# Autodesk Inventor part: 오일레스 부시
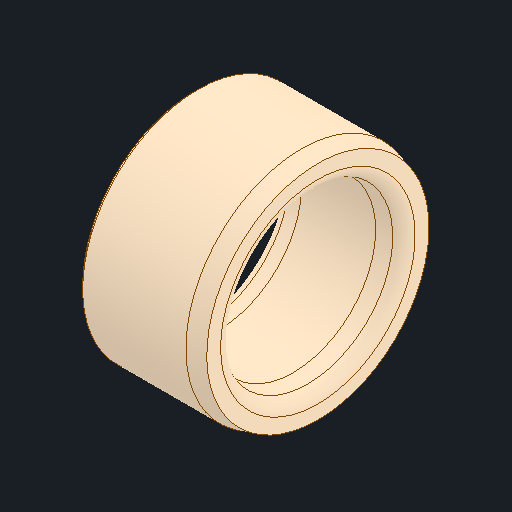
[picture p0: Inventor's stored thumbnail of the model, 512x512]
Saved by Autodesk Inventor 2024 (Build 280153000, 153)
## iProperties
Created: 2024-05
Part Number: 오일레스 부시
Material: 구리, 합금
Document SubType Name: Modeling
Designer: kh_501
Density: 8.92 g/cm^3
Appearance: 기본값
Author: jhkim
Sending System: Autodesk Inventor 2025
Preprocessor: ST-DEVELOPER v20
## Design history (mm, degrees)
feature "솔리드1"
node "솔리드2"
